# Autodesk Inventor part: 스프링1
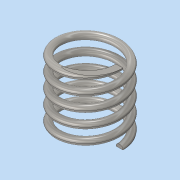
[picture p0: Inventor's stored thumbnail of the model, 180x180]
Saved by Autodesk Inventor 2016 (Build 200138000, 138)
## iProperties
Created: 2019-11
Part Number: 스프링1
Material: 스테인레스 스틸
Document SubType Name: Modeling
Designer: user
Density: 8 g/cm^3
Appearance: 반연마
Mass: 6.57245 g
Surface Area: 16.7217 cm^2
Volume: 0.821556 cm^3
Author: user
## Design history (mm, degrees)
sketch "스케치1"
  geometry: L1 (0, 0)-(8.5, 0); L2 (8.5, 0)-(8.5, 20.5); L3 (8.5, 20.5)-(0, 20.5); L4 (0, 20.5)-(0, 0); C1 r 1 at (8.5, 0)
  constraints: 8 end point, 2 parallel, 1 centre point, 1 coincident, 1 horizontal, 1 perpendicular
  dimensions: "d0" = 17 diameter of L2 L4; "d1" = 20.5 distance between parallel lines of L1 L3 (derived); "d2" = 2 diameter of C1
feature "코일1" sketch "스케치1" pitch "d3" = 10; turns "d5" = 5; dims "d4" = 20.5 (= d1), "d6" = 0, angle "d7" = 90 deg, angle "d8" = 90 deg, "d9" = 0, "d10" = 0
sketch "스케치2"
  geometry: L1 (20.5, 11.695)-(0, 11.695); L2 (0, 11.695)-(0, -11.695); L3 (0, -11.695)-(20.5, -11.695); L4 (20.5, -11.695)-(20.5, 11.695); 2 further points
  constraints: 8 end point, 2 parallel, 1 coincident, 1 horizontal, 1 midpoint, 1 perpendicular
  dimensions: "d11" = 20.5 distance between parallel lines of L2 L4 (= d1)
extrude "돌출1" sketch "스케치2" stored distance "d12" = 42; taper "d13" = 0 deg
node "솔리드1"
